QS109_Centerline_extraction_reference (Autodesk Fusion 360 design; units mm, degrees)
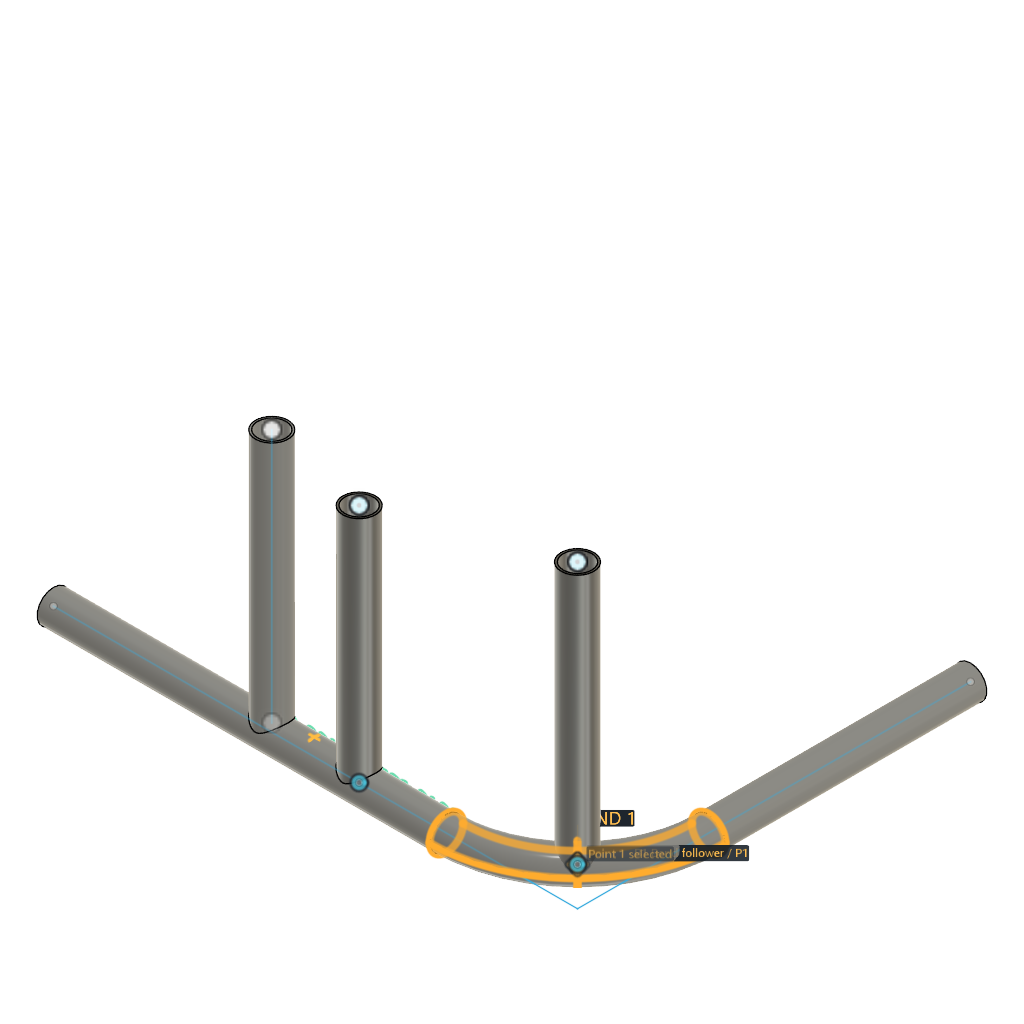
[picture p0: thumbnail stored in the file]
description: Part Number
part number: 2026-10-26-11-38-19-526
parameter "OD_DEMO_ONLY_1_5_x_095_R6" = 38.1
parameter "Wall_DEMO_ONLY_1_5_x_095_R6" = 2.413
base_feature "Base Feature1" bodies "H1 Bent host", "I1 Imported coped brace"
sketch "Tube points" plane through (0, 0, 0) normal (0, 0, 1) x axis (1, 0, 0)
sketch "TubePoints" plane through (0, 0, 0) normal (0, 0, 1) x axis (1, 0, 0)
work_plane "WorkPlane1" ExtraOffset 0
sketch "Sketch3" plane through (564.9631, 44.6369, 0) normal (0, 0, 1) x axis (0, 1, 0)
  circle C1 centre (0, 0) radius 19.05
  circle C2 centre (0, 0) radius 16.637
sketch "TubePoints (1)" plane through (0, 0, 0) normal (0, 0, 1) x axis (1, 0, 0)
work_plane "WorkPlane2" ExtraOffset 0
sketch "Sketch5" plane through (355.6, 0, 0) normal (0, 0, 1) x axis (0, 1, 0)
  circle C1 centre (0, 0) radius 19.05
  circle C2 centre (0, 0) radius 16.637
sketch "TubePoints (2)" plane through (0, 0, 0) normal (0, 0, 1) x axis (1, 0, 0)
work_plane "WorkPlane3" ExtraOffset 0
sketch "Sketch7" plane through (564.9631, 44.6369, 0) normal (0, 0, 1) x axis (0, 1, 0)
  circle C1 centre (0, 0) radius 19.05
  circle C2 centre (0, 0) radius 16.637
  dimension "d21" diameter C1 = 38.1 (= "OD_DEMO_ONLY_1_5_x_095_R6")
  dimension "d22" diameter C2 = 33.274 (= "OD_DEMO_ONLY_1_5_x_095_R6 - 2 * Wall_DEMO_ONLY_1_5_x_095_R6")
sweep "Sweep3" sketch "Sketch7" TwistAngle 0 TaperAngle 0 bodies "B1 Bend follower"
sketch "TubePoints (3)" plane through (0, 0, 0) normal (0, 0, 1) x axis (1, 0, 0)
work_plane "WorkPlane4" ExtraOffset 0
sketch "Sketch9" plane through (355.6, 0, 0) normal (0, 0, 1) x axis (0, 1, 0)
  circle C1 centre (0, 0) radius 19.05
  circle C2 centre (0, 0) radius 16.637
  dimension "d31" diameter C1 = 38.1 (= "OD_DEMO_ONLY_1_5_x_095_R6")
  dimension "d32" diameter C2 = 33.274 (= "OD_DEMO_ONLY_1_5_x_095_R6 - 2 * Wall_DEMO_ONLY_1_5_x_095_R6")
sweep "Sweep4" sketch "Sketch9" TwistAngle 0 TaperAngle 0 bodies "B2 Straight joint"
base_feature "Base Feature2"
surface_stitch "SurfaceStitch1" StitchingTolerence 0.01 bodies "normcope_B2_Straight_joint_A"
split "Split1" bodies "B2 Straight joint"
remove_body "RemoveBody1"
remove_body "RemoveBody2"
work_plane "WorkPlane5" AlongDistance -25.4 ExtraOffset 0
sketch "Centerline - H1 Bent host" plane through (0, 0, -25.4) normal (0, 0, 1) x axis (1, 0, 0)
  line L1 (609.6, 0) -> (0, 0)
  line L2 (609.6, 457.2) -> (609.6, 0)
work_plane "WorkPlane6" AlongDistance -16.0556 ExtraOffset 0
sketch "Centerline - I1 Imported coped brace" plane through (0, 0, -16.0556) normal (0, 0, 1) x axis (1, 0, 0)
named bodies: "H1 Bent host", "I1 Imported coped brace", "B1 Bend follower", "B2 Straight joint", "normcope_B2_Straight_joint_A"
